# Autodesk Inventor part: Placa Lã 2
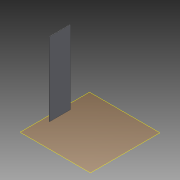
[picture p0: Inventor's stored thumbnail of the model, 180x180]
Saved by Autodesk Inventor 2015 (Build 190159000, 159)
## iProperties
Created: 2015-04
Part Number: Placa Lã 2
Material: Generic
Document SubType Name: Modeling
Designer: suporte
Density: 1 g/cm^3
Appearance: Default
Author: suporte
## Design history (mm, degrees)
workplane "Work Plane1"
sketch "Sketch1"
  geometry: L1 (-859.783, -312.5)-(-840.217, -312.5) reference; L2 (-840.466, 289.4)-(-859.534, 289.4) reference; L3 (-843.75, 289.4)-(-856.25, 289.4); L4 (-856.25, 289.4)-(-856.25, -312.5); L5 (-856.25, -312.5)-(-843.75, -312.5); L6 (-843.75, -312.5)-(-843.75, 289.4); 3 further points
  constraints: 8 end point, 2 midpoint, 2 parallel, 2 point on line, 1 coincident, 1 horizontal, 1 perpendicular
  dimensions: "d0" = 12.5 distance of L4.end L5.end
extrude "Extrusion1" new body sketch "Sketch1" distance "d1" = 2100; taper "d2" = 0 deg
body "Solid1"
node "Reference1"
node "Reference2"
